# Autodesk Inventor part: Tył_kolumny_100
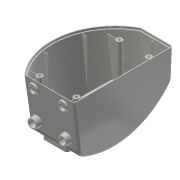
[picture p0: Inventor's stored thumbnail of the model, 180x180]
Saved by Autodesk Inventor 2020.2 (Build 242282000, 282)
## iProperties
Created: 2010-12
Part Number: Tył_kolumny_100
Document SubType Name: Modeling
Designer: F.Stasiak
Density: 1 g/cm^3
Material: Ogólny
Appearance: Gładkie — w kolorze kości słoniowej
Manager: www.cadconsulting.pl
Company: Fabian Stasiak CAD Consulting
Author: F.Stasiak
Subject: Zbiór ćwiczeń. Autodesk Inventor 2020. Kurs podstawowy
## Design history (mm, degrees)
sketch "Szkic2"
  geometry: L1 (0, 6.364)-(0, 0); L2 (0, 0)-(-4.995, 0); L3 (-97.719, 0)-(-100, 0); L4 (-63.707, 200)-(-65.027, 200); L5 (0, 195.005)-(0, 200); L6 (0, 200)-(-4.995, 200); L7 (-97.719, 0)-(-4.995, 0); L8 (0, 195.005)-(0, 6.364); L9 (-4.995, 200)-(-63.707, 200); A1 r 130 centre (-2.514, 86.002) between (-101.523, 1.758) and (-100, 0); A2 r 130 centre (-129.792, 312.719) between (-66.153, 199.361) and (-65.027, 200); A3 r 130 centre (-2.514, 86.002) between (-66.153, 199.361) and (-101.523, 1.758); 1 further point
  constraints: 18 end point, 6 point on circle, 5 perpendicular, 3 centre point, 2 coincident, 2 equal radius, 2 parallel, 1 collinear, 1 vertical
  dimensions: "d74" = 200 distance between parallel lines of L9 L7; "d75" = 100 distance of L1.end L3.end
extrude "Wyciągnięcie proste1" join sketch "Szkic2" distance "d1" = 110; taper "d2" = 0 deg
sketch "Szkic3"
  geometry: L1 (200, 0)-(200, -110) reference; L2 (0, 0)-(0, -110) reference; A1 r 145.689 centre (80.112, 27.778) between (0, -93.908) and (200, -55)
  constraints: 2 point on circle, 1 centre point, 1 point on line
feature "PowWyciągnięciaProstego1" sketch "Szkic3" dims "d3" = 140, "d4" = 0
feature "Wydłuż1" dims "d5" = 12.5
feature "Zamień powierzchnię1"
feature "Pochylenie ściany1" dims angle "d6" = 2.5 deg
feature "Pochylenie ściany2" dims angle "d7" = 6 deg
fillet "Zaokrąglenie1" dims "d13" = 20
fillet "Zaokrąglenie2" dims "d14" = 5
feature "Skorupa2" dims "d17" = 3.5
node "Płaszczyzna konstrukcyjna1"
sketch "Szkic6"
  geometry: L1 (81.347, -15)-(21.347, -15); L2 (21.347, -15)-(21.347, -75); L3 (21.347, -75)-(81.347, -75); L4 (81.347, -75)-(81.347, -15); L5 (97.729, 0)-(5, 0) reference; C1 r 9 at (81.347, -15); C2 r 9 at (21.347, -15); C3 r 9 at (81.347, -75); C4 r 9 at (21.347, -75); C5 r 7 at (81.347, -15); C6 r 7 at (21.347, -15); C7 r 7 at (81.347, -75); C8 r 7 at (21.347, -75); 3 further points
  constraints: 8 centre point, 8 coincident, 8 end point, 6 equal radius, 2 parallel, 1 horizontal, 1 midpoint, 1 perpendicular, 1 vertical alignment
  dimensions: "d20" = 60 distance of L3.end L2.end; "d21" = 60 distance of L2.end L1.end; "d23" = 18 diameter of C1; "d24" = 2 radial gap between concentric circles of C1 C5; "d76" = 15 distance between parallel lines of L5 L1
extrude "Wyciągnięcie proste3" join sketch "Szkic6" stored distance "d25" = 140; taper "d26" = 5 deg
fillet "Zaokrąglenie4" dims "d27" = 1
node "Płaszczyzna konstrukcyjna2"
sketch "Szkic8"
  geometry: L1 (-92.492, 23.503)-(-92.492, 2.565); L2 (-92.492, 23.503)-(-111.002, 23.503); L3 (-18.503, 23.503)-(-18.503, 2.565); L4 (-18.503, 23.503)-(0.006, 23.503); L5 (-75.095, 166.497)-(-100.905, 166.497); L6 (-15.503, 166.497)-(-2.13, 166.497); 1 further point
  constraints: 12 end point, 3 perpendicular, 2 equal length, 1 collinear, 1 parallel, 1 vertical
feature "Żebro2" dims "d47" = 1, "d48" = 1, "d49" = 0
node "Płaszczyzna konstrukcyjna3"
sketch "Szkic9"
  geometry: L1 (0, 189.388)-(0, 23.205) reference; L2 (-97.468, 4.045)-(-5, 4.045) reference; L3 (-3.5, 5.553)-(-3.5, 194.777) reference; L4 (-5, 196.278)-(-62.98, 196.278) reference; L5 (0, 194.777)-(0, 5.553) reference; L6 (-5, 0.526)-(-18.771, 0.526) reference; L7 (-63.001, 199.782)-(-5, 199.782) reference; L8 (-3.5, 100.165)-(-127.67, 100.165); L9 (-3.5, 135.165)-(-8.5, 135.165); L10 (-3.5, 65.165)-(-8.5, 65.165); L11 (-118.478, 135.165)-(-108.478, 135.165); L12 (-126.733, 65.165)-(-116.733, 65.165); L13 (-34.001, 194.777)-(-34.001, 189.777); L14 (-51.234, 4.045)-(-51.234, 12.045); L15 (-23.923, 0.526)-(-78.771, 0.526) reference; L16 (-83.923, 0.526)-(-97.486, 0.526) reference; A1 r 125.955 centre (-2.514, 86.002) between (-63.718, 196.088) and (-98.606, 4.572) reference; A2 r 129.474 centre (-2.514, 86.002) between (-65.461, 199.145) and (-101.279, 2.283) reference; 5 further points; 4 other entities
  constraints: 14 end point, 5 parallel, 3 point on circle, 2 collinear, 2 horizontal alignment, 2 midpoint, 2 point on line, 1 horizontal, 1 perpendicular, 8 other
  dimensions: "d102" = 5 distance of L9.start L9.end; "d103" = 5 distance of L10.start L10.end; "d104" = 70 distance from line of L10.end L9; "d105" = 35 distance between parallel lines of L9 L8 (= 0.5 x d104); "d106" = 10 distance of L11.start L11.end; "d107" = 10 distance of L12.start L12.end; "d108" = 5 distance of L13.start L13.end; "d109" = 8 distance of L14.start L14.end
feature "Żebro3" sketch "Szkic9" dims "d110" = 1, "d111" = 1, "d112" = 0
fillet "Zaokrąglenie6" dims "d113" = 3
node "Płaszczyzna konstrukcyjna4"
sketch "SZKIC KOMINKÓW MONTAŻOWYCH"
  geometry: 5 further points
sketch "SZKIC PÓŁKI"
  geometry: L1 (-75.498, 56.503)-(-35.498, 56.503); L2 (-30.498, 51.503)-(-30.498, 21.503); L3 (-35.498, 16.503)-(-75.498, 16.503); L4 (-80.498, 21.503)-(-80.498, 51.503); L5 (-92.492, 23.503)-(-18.503, 23.503); A1 r 5 centre (-35.498, 51.503) between (-30.498, 51.503) and (-35.498, 56.503); A2 r 5 centre (-75.498, 51.503) between (-75.498, 56.503) and (-80.498, 51.503); A3 r 5 centre (-35.498, 21.503) between (-35.498, 16.503) and (-30.498, 21.503); A4 r 5 centre (-75.498, 21.503) between (-80.498, 21.503) and (-75.498, 16.503); 6 further points
  constraints: 10 end point, 8 point on circle, 8 tangent, 6 point on line, 4 centre point, 3 equal radius, 2 midpoint, 2 parallel, 1 horizontal, 1 perpendicular, 1 vertical alignment
  dimensions: "d115" = 40 distance of point (-30.498, 56.503) point (-30.498, 16.503); "d116" = 50 distance of point (-30.498, 16.503) point (-80.498, 16.503); "d117" = 5 radius of A1; "d175" = 7 distance between parallel lines of L5 L3
feature "Kominek2" dims "d152" = 0, "d153" = 7.54, "d154" = 2, "d155" = 1.5, "d156" = 5.5, "d157" = 1.25, "d158" = 3.5, "d159" = 0.5 deg, "d160" = 0.5 deg, "d161" = 2.5 deg, "d162" = 2.5 deg, "d163" = 90 deg, "d166" = 1, "d167" = 30, "d168" = 8, "d169" = 0, "d170" = 2.5 deg, "d171" = 0.5 deg, "d172" = 0, "d173" = 0, "d174" = 0, "d211" = 0, "d212" = 360 deg
feature "Półka3" dims "d176" = 5, "d177" = 0, "d178" = 0, "d179" = 0, "d180" = 2.5 deg, "d181" = 2.5 deg, "d182" = 2.5
sketch "Szkic14"
  geometry: L1 (37.617, -32.643)-(33.617, -32.643); L2 (33.617, -32.643)-(33.617, -27.643); L3 (33.617, -27.643)-(37.617, -27.643); L4 (37.617, -27.643)-(37.617, -32.643); 1 further point
  constraints: 8 end point, 2 parallel, 1 horizontal, 1 perpendicular
  dimensions: "d187" = 4 distance of L2.end L3.end; "d188" = 5 distance of L1.end L2.end
extrude "Wyciągnięcie proste5" cut sketch "Szkic14" extent not by distance; stored distance "d189" = 10; taper "d190" = 0 deg
sketch "Szkic15"
  geometry: L1 (37.617, -27.643)-(37.617, -32.643) reference; L2 (33.617, -32.643)-(33.617, -27.643) reference; 3 further points
  constraints: 2 midpoint
feature "Połączenie zatrzaskowe2" sketch "Szkic15" dims "d191" = 15, "d192" = 2.5, "d193" = 3, "d194" = 2, "d195" = 5, "d196" = 4, "d197" = 1, "d198" = 1, "d199" = 50 deg, "d200" = 50 deg
feature "Występ5" dims "d201" = 4, "d202" = 2, "d203" = 0, "d204" = 0, "d205" = 2.5 deg, "d206" = 0.5
body "Srf1"
node "Bryła1"
node "Rzutuj krawędzie tnące1"
other parameters: "d19" = -3, "d46" = -11, "d101" = -5
